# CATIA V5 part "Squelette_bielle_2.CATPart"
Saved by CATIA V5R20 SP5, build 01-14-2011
Part number: Squelette_bielle_2
Publications: "Point.1", "Point.2", "Droite.1", "Droite.2", "Droite.3", "Plan xy", "Plan yz", "Plan zx"
Bounding box of the stored display mesh (mm): x 0 to 104, y 0 to 20, z 0 to 0
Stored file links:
  C:\Users\MARLENE\Documents\IFMA\S3\IAO\Copie de CAO\Squelette_bielle_2.CATPart
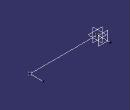
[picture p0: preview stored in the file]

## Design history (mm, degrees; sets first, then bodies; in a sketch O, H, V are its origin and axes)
Set1
  Point1: (0, 0, 0)
  Point2: (104, 0, 0)
  Line1: type PtPt, FirstPoint Point1, SecondPoint Point2
  Line2: type PtDir, RefPoint Point1, Direction zx-plane, Start 0, End 20
  Line3: type PtDir, RefPoint Point2, Direction zx-plane, Start 0, End 20
  Plane1: type Offset, RefPlane zx-plane, Offset 9
Body1 (main body)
